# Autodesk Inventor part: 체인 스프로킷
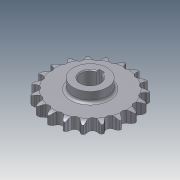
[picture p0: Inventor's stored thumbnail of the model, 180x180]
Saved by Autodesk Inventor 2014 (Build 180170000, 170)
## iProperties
Created: 2013-01
Part Number: 체인 스프로킷
Material: 강
Document SubType Name: Modeling
Designer: KYOUNG IL JANG
Density: 1 g/cm^3
Appearance: 강철
CustomPartVersion: 1
Company: 한국ATC센터
Author: KYOUNG IL JANG
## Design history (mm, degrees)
sketch "이론적 톱니 프로파일"
  geometry: L1 (0, 0)-(0, 45.567); L2 (0, 0)-(14.795, 43.098); L3 (0, 45.567)-(14.795, 43.098); L4 (0, 45.567)-(5.661, 50.015); L5 (5.661, 50.015)-(-5.141, 45.406); L6 (-12.428, 43.493)-(-5.573, 46.417); L7 (-5.141, 45.406)-(-5.573, 46.417); L8 (5.573, 46.417)-(5.141, 45.406); L9 (0, 0)-(8.138, 48.771); A1 r 45.567 centre (0, 0) between (0, 45.567) and (14.795, 43.098); A2 r 49.445 centre (0, 0) between (7.302, 48.903) and (-7.302, 48.903); A3 r 4.545 centre (0, 45.567) between (-3.574, 42.758) and (3.574, 42.758); A4 r 7.453 centre (12.428, 43.493) between (7.302, 48.903) and (5.573, 46.417); A5 r 7.453 centre (-12.428, 43.493) between (-5.573, 46.417) and (-7.302, 48.903); A6 r 11.745 centre (5.661, 50.015) between (-5.141, 45.406) and (-3.574, 42.758); A7 r 11.745 centre (-5.661, 50.015) between (3.574, 42.758) and (5.141, 45.406); 2 further points
  constraints: 18 end point, 15 point on circle, 7 centre point, 3 coincident, 3 point on line, 3 symmetric about line, 3 tangent, 1 equal radius, 1 midpoint, 1 parallel, 1 vertical, 1 other
  dimensions: "d0" = 91.13301 diameter of A1 (computed from da_p, da_z); "d2" = 18.9474 deg angle of L2 L1 (computed from da_z); "d3" = 4.545 radius of A3 (= 0.5 x da_Dr + da_SC); "d10" = 128.158 deg angle of L4 L1 (computed from da_z); "d11" = 15.0526 deg angle of L5 L4 (computed from da_z); "d12" = 7.2 distance of L3.start L4.end (= 0.8 x da_Dr); "d13" = 11.745 distance of L4.end L5.end (= 1.3 x da_Dr + da_SC); "d14" = 12.6 distance of A4.centre L1.end (= 1.4 x da_Dr); "d23" = 4.5 distance from line of L9.end L3 (= da_Ha)
sketch "톱니 프로파일"
  geometry: L1 (0, 0)-(0, 45.567); L2 (0, 45.567)-(4.203, 43.837); L3 (0, 45.567)-(-4.203, 43.837); A1 r 4.545 centre (0, 45.567) between (-4.203, 43.837) and (4.203, 43.837); A2 r 22.68 centre (25.176, 35.206) between (7.12, 48.93) and (4.203, 43.837); A3 r 22.68 centre (-25.176, 35.206) between (-4.203, 43.837) and (-7.12, 48.93); A4 r 49.445 centre (0, 0) between (-7.12, 48.93) and (7.12, 48.93) reference; 1 further point
  constraints: 9 point on circle, 6 end point, 3 centre point, 2 tangent, 1 coincident, 1 equal radius, 1 vertical, 1 other
  dimensions: "d44" = 135.263 deg angle of L3 L2 (= da_Alfa); "d45" = 22.68 radius of A2 (= da_Re); "d46" = 4.545 radius of A1 (= da_Ri)
sketch "단면 프로파일"
  geometry: L1 (49.445, 0)-(-49.445, 0) reference; L2 (33.265, 6.65)-(-33.265, 6.65); L3 (-33.265, 6.65)-(-33.265, -6.65); L4 (-33.265, -6.65)-(33.265, -6.65); L5 (33.265, -6.65)-(33.265, 6.65); L6 (33.265, 6.65)-(49.445, 6.65); L7 (49.445, 6.65)-(49.445, -6.65); L8 (49.445, -6.65)-(33.265, -6.65); L9 (33.265, -6.65)-(33.265, 6.65); L10 (42.183, 6.65)-(0, 6.65); L11 (0, 6.65)-(0, -6.65); L12 (0, -6.65)-(42.183, -6.65); L13 (0, 6.65)-(0, -6.65); L14 (49.445, 4.775)-(49.445, -4.775); A1 r 15 centre (42.183, -8.35) between (49.445, 4.775) and (42.183, 6.65); A2 r 15 centre (42.183, 8.35) between (42.183, -6.65) and (49.445, -4.775); 2 further points
  constraints: 26 end point, 7 midpoint, 5 perpendicular, 4 parallel, 4 point on circle, 3 point on line, 3 symmetric about line, 2 centre point, 2 horizontal, 2 tangent, 1 collinear, 1 other
  dimensions: "d30" = 13.3 distance between parallel lines of L8 L6 (= da_Bf); "d31" = 66.53007 distance between parallel lines of L3 L5 (= da_Ds); "d32" = 13.3 distance between parallel lines of L4 L2 (= da_Bs); "d33" = 1.875 distance from line of L14.start L6 (= da_Ba); "d34" = 15 radius of A1 (= da_Rx); "d43" = 6.65 distance between parallel lines of L4 L1 (computed from da_k, da_pt, da_Bs)
revolve "슈라우드" stored, may be unused: angle "d36" = 90 deg
revolve "스트랜드" stored, may be unused: angle "d37" = 90 deg
extrude "이론적 톱니" cut sketch "이론적 톱니 프로파일" stored distance "d18" = 10; taper "d19" = 0 deg; dims "d49" = 0, "form_type" = 0 [user parameter]
extrude "톱니" cut sketch "톱니 프로파일" stored distance "d47" = 10; taper "d48" = 0 deg; dims "d50" = 10, "form_type" = 0 [user parameter]
node "타이밍 평면"
node "작업 평면3"
sketch "스케치5"
  geometry: C1 r 20 at (0, -45.567); 1 further point
  constraints: 1 centre point, 1 coincident
  dimensions: "d52" = 40 diameter of C1
extrude "돌출4" join sketch "스케치5" stored distance "d53" = 10; taper "d54" = 0 deg
sketch "스케치6"
  geometry: L1 (3, 10.583)-(3, 13.8); L2 (3, 13.8)-(-3, 13.8); L3 (-3, 13.8)-(-3, 10.583); A1 r 11 centre (0, 0) between (3, 10.583) and (-3, 10.583); 1 further point
  constraints: 6 end point, 2 parallel, 2 point on circle, 1 centre point, 1 coincident, 1 perpendicular, 1 vertical
  dimensions: "d55" = 22 diameter of A1; "d56" = 24.8 dimension on A1 L2 (computed from d55); "d57" = 6 distance of L1.end L2.end
extrude "돌출5" cut sketch "스케치6" stored distance "d58" = 10; taper "d59" = 0 deg
fillet "모깎기2" dims "d60" = 3
chamfer "모따기1" distance "d61" = 1; stored, may be unused: second distance "d62" = 2, angle "d63" = 45 deg
body "Solid1"
pattern_linear "스트랜드 패턴" dims "d40" = 24 (= da_pt)
pattern_circular "톱니 패턴" dims angle "d21" = 360 deg
other parameters: "da_p" = 15 [user parameter; used in 1 equation term], "da_Dr" = 9 [user parameter; used in 4 equation terms], "da_SC" = 0.045 [user parameter; used in 2 equation terms], "da_Ha" = 4.5 [user parameter; used in 1 equation term], "da_pt" = 24 [user parameter; used in 2 equation terms], "da_Bf" = 13.3 [user parameter; used in 1 equation term], "d28" = 0, "d29" = 0, "da_Ba" = 1.875 [user parameter; used in 1 equation term], "da_Rx" = 15 [user parameter; used in 1 equation term], "da_Ra" = 0.6 [user parameter], "da_Bs" = 13.3 [user parameter; used in 2 equation terms], "da_Ds" = 66.53007 [user parameter; used in 1 equation term], "d42" = 0, "da_Re" = 22.68 [user parameter; used in 1 equation term], "da_Ri" = 4.545 [user parameter; used in 1 equation term], "da_Alfa" = 135.263 deg [user parameter; used in 1 equation term], "d51" = -25
